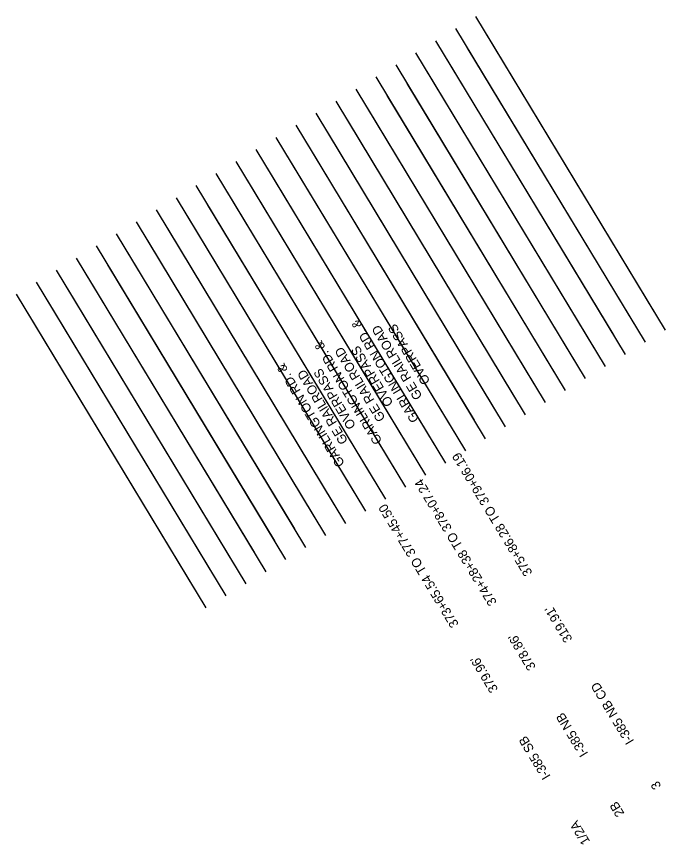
# Model space of a CAD drawing. Extents: x 2640307 to 2643631, y 679117 to 682232.
# Drawn here: x 2642632 to 2643159, y 679117 to 679788 of the extents above; entities that cross this region are included whole.
import ezdxf

# ---------------------------------------------------------------- set-up
doc = ezdxf.new("R2010")
doc.units = 0
doc.layers.add('Level 3', color=7, linetype='Continuous')
doc.layers.add('Level 63', color=7, linetype='Continuous')

msp = doc.modelspace()

# ---------------------------------------------------------------- linework, layer by layer
at = {"layer": 'Level 63'}
for p, q in [((2643149.34, 679548.82), (2643004.85, 679787.86)), ((2643133.15, 679539.04), (2642988.66, 679778.07)), ((2643116.95, 679529.24), (2642972.47, 679768.28)), ((2643158.5, 679533.66), (2643014.01, 679772.7)), ((2643142.31, 679523.87), (2642997.83, 679762.91)), ((2643100.75, 679519.46), (2642956.26, 679758.49)), ((2643084.56, 679509.67), (2642940.08, 679748.7)), ((2643126.12, 679514.08), (2642981.63, 679753.12)), ((2643109.92, 679504.3), (2642965.43, 679743.33)), ((2643068.37, 679499.87), (2642923.88, 679738.91)), ((2643052.17, 679490.09), (2642907.68, 679729.12)), ((2643093.73, 679494.51), (2642949.24, 679733.54)), ((2643077.53, 679484.71), (2642933.04, 679723.75)), ((2643035.98, 679480.3), (2642891.5, 679719.33)), ((2643061.33, 679474.93), (2642916.85, 679713.96)), ((2643019.78, 679470.51), (2642875.3, 679709.54)), ((2643045.14, 679465.14), (2642900.66, 679704.17)), ((2643003.58, 679460.72), (2642859.12, 679699.75)), ((2643028.95, 679455.35), (2642884.46, 679694.38)), ((2642987.39, 679450.93), (2642842.91, 679689.97)), ((2642971.2, 679441.14), (2642826.71, 679680.17)), ((2643012.75, 679445.56), (2642868.28, 679684.59)), ((2642996.56, 679435.77), (2642852.08, 679674.81)), ((2642955.01, 679431.36), (2642810.53, 679670.39)), ((2642938.81, 679421.56), (2642794.33, 679660.6)), ((2642980.36, 679425.98), (2642835.88, 679665.01)), ((2642964.17, 679416.2), (2642819.69, 679655.22)), ((2642922.61, 679411.78), (2642778.13, 679650.81)), ((2642906.49, 679402.04), (2642762.02, 679641.07)), ((2642947.98, 679406.4), (2642803.49, 679645.44)), ((2642931.77, 679396.61), (2642787.3, 679635.65)), ((2642890.31, 679392.26), (2642745.83, 679631.28)), ((2642874.12, 679382.47), (2642729.63, 679621.5)), ((2642915.66, 679386.88), (2642771.18, 679625.91)), ((2642899.48, 679377.1), (2642754.99, 679616.12)), ((2642857.92, 679372.68), (2642713.43, 679611.72)), ((2642883.29, 679367.31), (2642738.79, 679606.34)), ((2642841.73, 679362.89), (2642697.24, 679601.92)), ((2642867.09, 679357.52), (2642722.6, 679596.56)), ((2642825.54, 679353.1), (2642681.04, 679592.13)), ((2642850.89, 679347.73), (2642706.4, 679586.76)), ((2642809.33, 679343.31), (2642664.84, 679582.34)), ((2642834.71, 679337.94), (2642690.21, 679576.97)), ((2642793.14, 679333.53), (2642648.65, 679572.56)), ((2642818.5, 679328.14), (2642674.01, 679567.18)), ((2642776.95, 679323.74), (2642632.46, 679562.78)), ((2642802.3, 679318.37), (2642657.81, 679557.4)), ((2642786.11, 679308.58), (2642641.62, 679547.62))]:
    msp.add_line(p, q, dxfattribs=at)

# ---------------------------------------------------------------- texts
at = {"layer": 'Level 3'}
for s, p in [('GARLINGTON RD. & ', (2642959.11, 679461.58)), ('GE RAILROAD', (2642961.73, 679480.02)), ('OVERPASS', (2642968.11, 679492.25)), ('GARLINGTON RD. & ', (2642929.14, 679443.83)), ('GE RAILROAD', (2642931.76, 679462.27)), ('OVERPASS', (2642938.14, 679474.51)), ('GARLINGTON RD. & ', (2642898.79, 679425.51)), ('GE RAILROAD', (2642901.42, 679443.95)), ('OVERPASS', (2642907.79, 679456.18)), ('375+86.28 TO 379+06.19', (2643050.91, 679337.06)), ('374+28+38 TO 378+07.24', (2643022.07, 679313.07)), ('373+65.54 TO 377+45.50', (2642991.25, 679295.34)), ("319.91'", (2643083.38, 679283.33)), ("378.86'", (2643053.72, 679260.7)), ("379.96'", (2643023.11, 679242.62)), ('I-385 NB CD', (2643133.34, 679200.68)), ('I-385 NB', (2643096.1, 679190.59)), ('I-385 SB', (2643065.68, 679172.2)), ('3', (2643155.39, 679164.21)), ('2B', (2643125.48, 679141.99)), ('1/2A', (2643097.65, 679119.31))]:
    msp.add_text(s, height=7.5, rotation=121.15134, dxfattribs=at).set_placement(p)

doc.saveas('drawing.dxf')
